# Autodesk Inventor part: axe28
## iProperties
Shininess: 21.0
Length Units: 11269
Angle Units: 11279
Time Units: 11290
Mass Units: 11283
Length Display Precision: 3
Angle Display Precision: 2
Compacted: True
Created: 2001-12
Part Number: axe28
Material: Par défaut
Document SubType Name: Modélisation
Designer: pichon
Density: 0.0
Volumn: 0.0
Area: 0.0
PropertySet Name: Model Information
Control State: 0
Master: False
Checked Out: False
Author: pichon
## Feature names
1. Extrusion1
2. Extrusion2
3. Chanfrein1 [Chamfer]
4. Extrusion3
